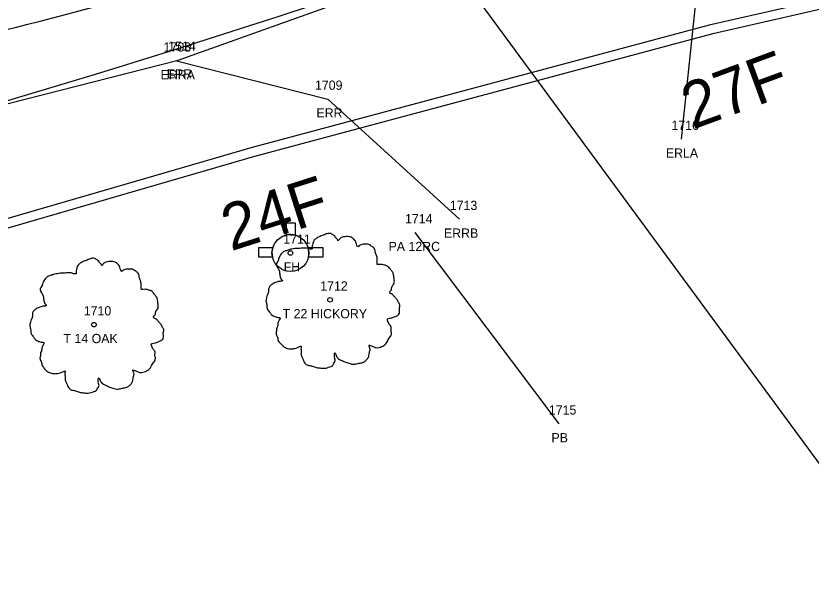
# Model space of a CAD drawing. Extents: x 1964982 to 1970452, y 1116335 to 1119906.
# Drawn here: x 1966704.1 to 1966790.2, y 1117364.6 to 1117427.6 of the extents above; entities that cross this region are included whole.
import ezdxf

# ---------------------------------------------------------------- set-up
doc = ezdxf.new("R2010")
doc.units = 0
for name, color, linetype in [('RD_EX_DR_Pipe', 7, 'Continuous'), ('RD_EX_DR_Pipe_txCode', 7, 'Continuous'), ('RD_EX_DV_Prop', 7, 'Continuous'), ('RD_EX_Road', 7, 'Continuous'), ('RD_EX_Road_txCode', 7, 'Continuous'), ('RD_EX_RW', 7, 'Continuous'), ('RD_EX_UT', 7, 'Continuous'), ('RD_EX_UT_txCode', 7, 'Continuous'), ('RD_EX_VEG', 7, 'Continuous'), ('RD_EX_VEG_txCode', 7, 'Continuous'), ('RD_HC_CL', 7, 'Continuous'), ('RD_HC_CL_Rel', 7, 'Continuous'), ('RD_PD_CstnLmt', 7, 'Continuous'), ('RD_PD_Final_TrvlWay', 7, 'Continuous'), ('RD_PD_RW', 7, 'Continuous'), ('RD_PD_TX_CstnLmt', 7, 'Continuous'), ('RD_SMD_Locator', 7, 'Continuous')]:
    doc.layers.add(name, color=color, linetype=linetype)

msp = doc.modelspace()

# ---------------------------------------------------------------- linework, layer by layer
at = {"layer": 'RD_EX_DR_Pipe'}
msp.add_line((1966747.303, 1117404.166), (1966762.879, 1117383.468), dxfattribs=at)
at = {"layer": 'RD_EX_DV_Prop'}
msp.add_line((1966745.73, 1117440.789), (1967101.344, 1116957.456), dxfattribs=at)
msp.add_arc((1966579.594, 1117921.318), 510.35, 281.90473, 291.99584, dxfattribs=at)
at = {"layer": 'RD_EX_Road'}
for points in [[(1966776.172, 1117414.279), (1966777.92, 1117430.838), (1966787.296, 1117445.194)], [(1965729.992, 1117080.297), (1965819.77, 1117119.134), (1965907.737, 1117159.312), (1965995.365, 1117199.039), (1966039.268, 1117218.497), (1966081.241, 1117237.148), (1966124.665, 1117256.555), (1966167.659, 1117275.555), (1966211.467, 1117293.627), (1966257.791, 1117311.581), (1966302.7, 1117327.207), (1966347.903, 1117339.982), (1966394.806, 1117351.637), (1966441.557, 1117361.865), (1966488.625, 1117372.057), (1966534.906, 1117381.34), (1966581.234, 1117390.947), (1966629.533, 1117400.947), (1966675.632, 1117411.107), (1966721.676, 1117422.847), (1966766.802, 1117438.972), (1966775.751, 1117440.571)], [(1966721.496, 1117422.751), (1966737.884, 1117418.624), (1966752.157, 1117405.613)]]:
    msp.add_lwpolyline(points, dxfattribs=at)
at = {"layer": 'RD_EX_RW'}
msp.add_lwpolyline([(1965729.992, 1117080.297), (1965819.77, 1117119.134), (1965907.737, 1117159.312), (1965995.365, 1117199.039), (1966039.268, 1117218.497), (1966081.241, 1117237.148), (1966124.665, 1117256.555), (1966167.659, 1117275.555), (1966211.467, 1117293.627), (1966257.791, 1117311.581), (1966302.7, 1117327.207), (1966347.903, 1117339.982), (1966394.806, 1117351.637), (1966441.557, 1117361.865), (1966488.625, 1117372.057), (1966534.906, 1117381.34), (1966581.234, 1117390.947), (1966629.533, 1117400.947), (1966675.632, 1117411.107), (1966721.676, 1117422.847), (1966766.802, 1117438.972), (1966775.751, 1117440.571)], dxfattribs=at)
at = {"layer": 'RD_EX_UT'}
for p, q in [((1966733.383, 1117405.18), (1966733.383, 1117403.906)), ((1966734.383, 1117405.18), (1966733.383, 1117405.18)), ((1966734.383, 1117403.884), (1966734.383, 1117405.18)), ((1966731.924, 1117402.533), (1966730.367, 1117402.533)), ((1966730.367, 1117402.533), (1966730.367, 1117401.533)), ((1966737.367, 1117402.533), (1966735.756, 1117402.533)), ((1966737.367, 1117401.533), (1966737.367, 1117402.533)), ((1966730.367, 1117401.533), (1966731.886, 1117401.533)), ((1966735.794, 1117401.533), (1966737.367, 1117401.533))]:
    msp.add_line(p, q, dxfattribs=at)
for radius in [2, 0.25]:
    msp.add_circle((1966733.84, 1117401.959), radius, dxfattribs=at)
for start, end in [(74.24553, 103.21276), (163.3387, 192.31502), (347.68498, 16.6613)]:
    msp.add_arc((1966733.84, 1117401.959), 2, start, end, dxfattribs=at)
at = {"layer": 'RD_EX_VEG'}
for centre, radius in [((1966738.129, 1117396.891), 0.25), ((1966738.116, 1117396.872), 0.0001), ((1966712.568, 1117394.203), 0.25), ((1966712.556, 1117394.184), 0.0001)]:
    msp.add_circle(centre, radius, dxfattribs=at)
for points in [[(1966738.261, 1117404.058), (1966737.961, 1117404.083), (1966737.636, 1117403.983), (1966737.386, 1117403.883), (1966737.161, 1117403.808), (1966736.937, 1117403.708), (1966736.637, 1117403.534), (1966736.412, 1117403.334), (1966736.287, 1117403.084), (1966736.237, 1117402.859), (1966736.187, 1117402.584), (1966736.187, 1117402.409), (1966736.062, 1117402.384), (1966735.912, 1117402.409), (1966735.662, 1117402.484), (1966735.412, 1117402.484), (1966735.162, 1117402.484), (1966734.812, 1117402.459), (1966734.463, 1117402.459), (1966734.188, 1117402.409), (1966733.863, 1117402.359), (1966733.488, 1117402.234), (1966733.138, 1117402.109), (1966732.838, 1117401.859), (1966732.588, 1117401.384), (1966732.463, 1117401.035), (1966732.314, 1117400.785), (1966732.463, 1117400.335), (1966732.638, 1117399.985), (1966732.663, 1117399.785), (1966732.738, 1117399.36), (1966732.838, 1117399.135), (1966732.963, 1117398.935), (1966732.888, 1117398.911), (1966732.513, 1117398.861), (1966732.214, 1117398.761), (1966731.789, 1117398.536), (1966731.564, 1117398.311), (1966731.464, 1117397.986), (1966731.439, 1117397.636), (1966731.339, 1117397.436), (1966731.264, 1117397.161), (1966731.239, 1117397.086), (1966731.189, 1117396.761), (1966731.289, 1117396.312), (1966731.314, 1117395.962), (1966731.439, 1117395.737), (1966731.589, 1117395.562), (1966731.764, 1117395.312), (1966732.164, 1117395.087), (1966732.488, 1117394.987), (1966732.688, 1117394.962), (1966732.513, 1117394.462), (1966732.463, 1117394.113), (1966732.339, 1117393.713), (1966732.339, 1117393.638), (1966732.289, 1117393.163), (1966732.438, 1117392.838), (1966732.513, 1117392.463), (1966732.688, 1117392.238), (1966732.963, 1117391.939), (1966733.288, 1117391.714), (1966733.788, 1117391.589), (1966734.188, 1117391.614), (1966734.763, 1117391.789), (1966735.012, 1117391.864), (1966734.987, 1117391.689), (1966735.012, 1117391.314), (1966735.012, 1117390.889), (1966735.162, 1117390.564), (1966735.262, 1117390.289), (1966735.412, 1117390.039), (1966735.737, 1117389.815), (1966736.137, 1117389.74), (1966736.562, 1117389.59), (1966737.012, 1117389.515), (1966737.511, 1117389.49), (1966738.111, 1117389.64), (1966738.386, 1117389.765), (1966738.486, 1117389.939), (1966738.686, 1117390.314), (1966738.636, 1117390.539), (1966738.661, 1117391.139), (1966738.761, 1117390.964), (1966738.936, 1117390.614), (1966739.435, 1117390.314), (1966739.835, 1117390.139), (1966740.31, 1117389.989), (1966740.61, 1117389.914), (1966741.085, 1117389.989), (1966741.46, 1117390.064), (1966741.834, 1117390.189), (1966742.134, 1117390.464), (1966742.309, 1117390.739), (1966742.359, 1117391.014), (1966742.434, 1117391.389), (1966742.484, 1117391.564)], [(1966742.484, 1117391.564), (1966742.409, 1117391.739), (1966742.359, 1117391.989), (1966742.434, 1117391.964), (1966742.609, 1117391.914), (1966742.884, 1117391.789), (1966743.109, 1117391.714), (1966743.434, 1117391.739), (1966743.709, 1117391.839), (1966744.158, 1117392.114), (1966744.433, 1117392.588), (1966744.708, 1117392.988), (1966744.783, 1117393.313), (1966744.733, 1117393.538), (1966744.708, 1117394.038), (1966744.508, 1117394.288), (1966744.458, 1117394.412), (1966744.358, 1117394.812), (1966744.433, 1117394.862), (1966744.708, 1117394.912), (1966745.083, 1117395.037), (1966745.358, 1117395.162), (1966745.583, 1117395.337), (1966745.658, 1117395.562), (1966745.633, 1117395.962), (1966745.683, 1117396.362), (1966745.608, 1117396.512), (1966745.508, 1117396.661), (1966745.433, 1117396.861), (1966745.283, 1117397.011), (1966745.183, 1117397.161), (1966745.083, 1117397.261), (1966744.958, 1117397.411), (1966744.783, 1117397.536), (1966744.633, 1117397.586), (1966744.583, 1117397.736), (1966744.733, 1117397.936), (1966744.783, 1117398.036), (1966744.808, 1117398.261), (1966745.033, 1117398.611), (1966745.083, 1117399.01), (1966745.033, 1117399.435), (1966744.983, 1117399.71), (1966744.833, 1117399.985), (1966744.633, 1117400.235), (1966744.508, 1117400.41), (1966744.333, 1117400.535), (1966744.008, 1117400.66), (1966743.759, 1117400.71), (1966743.409, 1117400.71), (1966743.209, 1117400.76), (1966743.234, 1117400.81), (1966743.234, 1117400.96), (1966743.234, 1117401.235), (1966743.159, 1117401.684), (1966743.009, 1117402.184), (1966743.009, 1117402.209), (1966742.909, 1117402.459), (1966742.684, 1117402.659), (1966742.509, 1117402.759), (1966742.309, 1117402.884), (1966742.059, 1117402.909), (1966741.759, 1117402.909), (1966741.485, 1117402.859), (1966741.285, 1117402.759), (1966741.11, 1117402.634), (1966741.035, 1117402.784), (1966740.935, 1117403.084), (1966740.885, 1117403.234), (1966740.735, 1117403.409), (1966740.51, 1117403.608), (1966740.06, 1117403.733), (1966739.435, 1117403.658), (1966739.136, 1117403.459), (1966738.986, 1117403.284), (1966738.936, 1117403.409), (1966738.736, 1117403.608), (1966738.636, 1117403.783), (1966738.461, 1117403.908), (1966738.311, 1117404.008), (1966738.211, 1117404.058)], [(1966712.7, 1117401.37), (1966712.4, 1117401.395), (1966712.075, 1117401.295), (1966711.826, 1117401.196), (1966711.601, 1117401.121), (1966711.376, 1117401.021), (1966711.076, 1117400.846), (1966710.851, 1117400.646), (1966710.726, 1117400.396), (1966710.676, 1117400.171), (1966710.626, 1117399.896), (1966710.626, 1117399.721), (1966710.501, 1117399.696), (1966710.351, 1117399.721), (1966710.101, 1117399.796), (1966709.851, 1117399.796), (1966709.601, 1117399.796), (1966709.252, 1117399.771), (1966708.902, 1117399.771), (1966708.627, 1117399.721), (1966708.302, 1117399.671), (1966707.927, 1117399.546), (1966707.577, 1117399.421), (1966707.278, 1117399.171), (1966707.028, 1117398.697), (1966706.903, 1117398.347), (1966706.753, 1117398.097), (1966706.903, 1117397.647), (1966707.078, 1117397.297), (1966707.103, 1117397.097), (1966707.178, 1117396.673), (1966707.278, 1117396.448), (1966707.402, 1117396.248), (1966707.328, 1117396.223), (1966706.953, 1117396.173), (1966706.653, 1117396.073), (1966706.228, 1117395.848), (1966706.003, 1117395.623), (1966705.903, 1117395.298), (1966705.878, 1117394.948), (1966705.778, 1117394.748), (1966705.703, 1117394.473), (1966705.678, 1117394.398), (1966705.628, 1117394.074), (1966705.728, 1117393.624), (1966705.753, 1117393.274), (1966705.878, 1117393.049), (1966706.028, 1117392.874), (1966706.203, 1117392.624), (1966706.603, 1117392.399), (1966706.928, 1117392.299), (1966707.128, 1117392.274), (1966706.953, 1117391.775), (1966706.903, 1117391.425), (1966706.778, 1117391.025), (1966706.778, 1117390.95), (1966706.728, 1117390.475), (1966706.878, 1117390.15), (1966706.953, 1117389.776), (1966707.128, 1117389.551), (1966707.402, 1117389.251), (1966707.727, 1117389.026), (1966708.227, 1117388.901), (1966708.627, 1117388.926), (1966709.202, 1117389.101), (1966709.452, 1117389.176), (1966709.427, 1117389.001), (1966709.452, 1117388.626), (1966709.452, 1117388.201), (1966709.601, 1117387.876), (1966709.701, 1117387.601), (1966709.851, 1117387.352), (1966710.176, 1117387.127), (1966710.576, 1117387.052), (1966711.001, 1117386.902), (1966711.451, 1117386.827), (1966711.95, 1117386.802), (1966712.55, 1117386.952), (1966712.825, 1117387.077), (1966712.925, 1117387.252), (1966713.125, 1117387.626), (1966713.075, 1117387.851), (1966713.1, 1117388.451), (1966713.2, 1117388.276), (1966713.375, 1117387.926), (1966713.875, 1117387.626), (1966714.274, 1117387.452), (1966714.749, 1117387.302), (1966715.049, 1117387.227), (1966715.524, 1117387.302), (1966715.899, 1117387.377), (1966716.274, 1117387.502), (1966716.573, 1117387.776), (1966716.748, 1117388.051), (1966716.798, 1117388.326), (1966716.873, 1117388.701), (1966716.923, 1117388.876)], [(1966716.923, 1117388.876), (1966716.848, 1117389.051), (1966716.798, 1117389.301), (1966716.873, 1117389.276), (1966717.048, 1117389.226), (1966717.323, 1117389.101), (1966717.548, 1117389.026), (1966717.873, 1117389.051), (1966718.148, 1117389.151), (1966718.598, 1117389.426), (1966718.872, 1117389.9), (1966719.147, 1117390.3), (1966719.222, 1117390.625), (1966719.172, 1117390.85), (1966719.147, 1117391.35), (1966718.947, 1117391.6), (1966718.897, 1117391.725), (1966718.797, 1117392.124), (1966718.872, 1117392.174), (1966719.147, 1117392.224), (1966719.522, 1117392.349), (1966719.797, 1117392.474), (1966720.022, 1117392.649), (1966720.097, 1117392.874), (1966720.072, 1117393.274), (1966720.122, 1117393.674), (1966720.047, 1117393.824), (1966719.947, 1117393.974), (1966719.872, 1117394.174), (1966719.722, 1117394.323), (1966719.622, 1117394.473), (1966719.522, 1117394.573), (1966719.397, 1117394.723), (1966719.222, 1117394.848), (1966719.072, 1117394.898), (1966719.022, 1117395.048), (1966719.172, 1117395.248), (1966719.222, 1117395.348), (1966719.247, 1117395.573), (1966719.472, 1117395.923), (1966719.522, 1117396.323), (1966719.472, 1117396.747), (1966719.422, 1117397.022), (1966719.272, 1117397.297), (1966719.072, 1117397.547), (1966718.947, 1117397.722), (1966718.772, 1117397.847), (1966718.448, 1117397.972), (1966718.198, 1117398.022), (1966717.848, 1117398.022), (1966717.648, 1117398.072), (1966717.673, 1117398.122), (1966717.673, 1117398.272), (1966717.673, 1117398.547), (1966717.598, 1117398.996), (1966717.448, 1117399.496), (1966717.448, 1117399.521), (1966717.348, 1117399.771), (1966717.123, 1117399.971), (1966716.948, 1117400.071), (1966716.748, 1117400.196), (1966716.498, 1117400.221), (1966716.199, 1117400.221), (1966715.924, 1117400.171), (1966715.724, 1117400.071), (1966715.549, 1117399.946), (1966715.474, 1117400.096), (1966715.374, 1117400.396), (1966715.324, 1117400.546), (1966715.174, 1117400.721), (1966714.949, 1117400.921), (1966714.499, 1117401.046), (1966713.875, 1117400.971), (1966713.575, 1117400.771), (1966713.425, 1117400.596), (1966713.375, 1117400.721), (1966713.175, 1117400.921), (1966713.075, 1117401.096), (1966712.9, 1117401.221), (1966712.75, 1117401.32), (1966712.65, 1117401.37)]]:
    msp.add_spline(points, degree=3, dxfattribs=at)
at = {"layer": 'RD_HC_CL'}
msp.add_arc((1966579.594, 1117921.318), 510.35, 281.90472, 291.99584, dxfattribs=at)
at = {"layer": 'RD_HC_CL_Rel'}
msp.add_arc((1966373.74, 1118527.456), 1145.915, 281.904723, 295.046328, dxfattribs=at)
at = {"layer": 'RD_PD_CstnLmt'}
for p, q in [((1966829.798, 1117438.199), (1966779.175, 1117426.61)), ((1966779.175, 1117426.61), (1966729.686, 1117413.368)), ((1966729.686, 1117413.368), (1966680.687, 1117399.137))]:
    msp.add_line(p, q, dxfattribs=at)
at = {"layer": 'RD_PD_Final_TrvlWay'}
for radius in [1134.915, 1156.915]:
    msp.add_arc((1966373.74, 1118527.456), radius, 281.904723, 295.046328, dxfattribs=at)
at = {"layer": 'RD_PD_RW'}
for p, q in [((1966830.151, 1117437.254), (1966779.415, 1117425.639)), ((1966779.415, 1117425.639), (1966729.954, 1117412.405)), ((1966729.954, 1117412.405), (1966680.946, 1117398.171))]:
    msp.add_line(p, q, dxfattribs=at)
at = {"layer": 'RD_SMD_Locator'}
for centre in [(1966721.496, 1117422.751), (1966721.676, 1117422.847), (1966721.676, 1117422.847), (1966737.884, 1117418.624), (1966776.172, 1117414.279), (1966752.157, 1117405.613), (1966747.303, 1117404.166), (1966762.879, 1117383.468)]:
    msp.add_circle(centre, 0.001, dxfattribs=at)

# ---------------------------------------------------------------- texts
at = {"layer": 'RD_EX_DR_Pipe_txCode'}
for s, p in [('1714', (1966746.24, 1117405.166)), ('PA 12RC', (1966744.461, 1117402.166)), ('1715', (1966761.816, 1117384.468)), ('PB', (1966762.1, 1117381.468))]:
    msp.add_text(s, height=1, dxfattribs=at).set_placement(p)
at = {"layer": 'RD_EX_Road_txCode'}
for s, p in [('1708', (1966720.11, 1117423.751)), ('1514', (1966720.613, 1117423.847)), ('1514', (1966720.613, 1117423.847)), ('ERRA', (1966719.78, 1117420.751)), ('EPR', (1966720.447, 1117420.847)), ('EPR', (1966720.447, 1117420.847)), ('1709', (1966736.498, 1117419.624)), ('ERR', (1966736.656, 1117416.624)), ('1716', (1966775.086, 1117415.279)), ('ERLA', (1966774.479, 1117412.279)), ('1713', (1966751.094, 1117406.613)), ('ERRB', (1966750.456, 1117403.613))]:
    msp.add_text(s, height=1, dxfattribs=at).set_placement(p)
at = {"layer": 'RD_EX_UT_txCode'}
for s, p in [('1711', (1966733.061, 1117402.959)), ('FH', (1966733.108, 1117399.959))]:
    msp.add_text(s, height=1, dxfattribs=at).set_placement(p)
at = {"layer": 'RD_EX_VEG_txCode'}
for s, p in [('1712', (1966737.066, 1117397.891)), ('1710', (1966711.466, 1117395.203)), ('T 22 HICKORY', (1966732.995, 1117394.891)), ('T 14 OAK', (1966709.269, 1117392.203))]:
    msp.add_text(s, height=1, dxfattribs=at).set_placement(p)
at = {"layer": 'RD_PD_TX_CstnLmt'}
for s, rotation, p in [('27F', 20.21843, (1966777.365, 1117415.287)), ('24F', 17.71843, (1966727.384, 1117402.134))]:
    msp.add_text(s, height=5, rotation=rotation, dxfattribs=at).set_placement(p)

doc.saveas('drawing.dxf')
